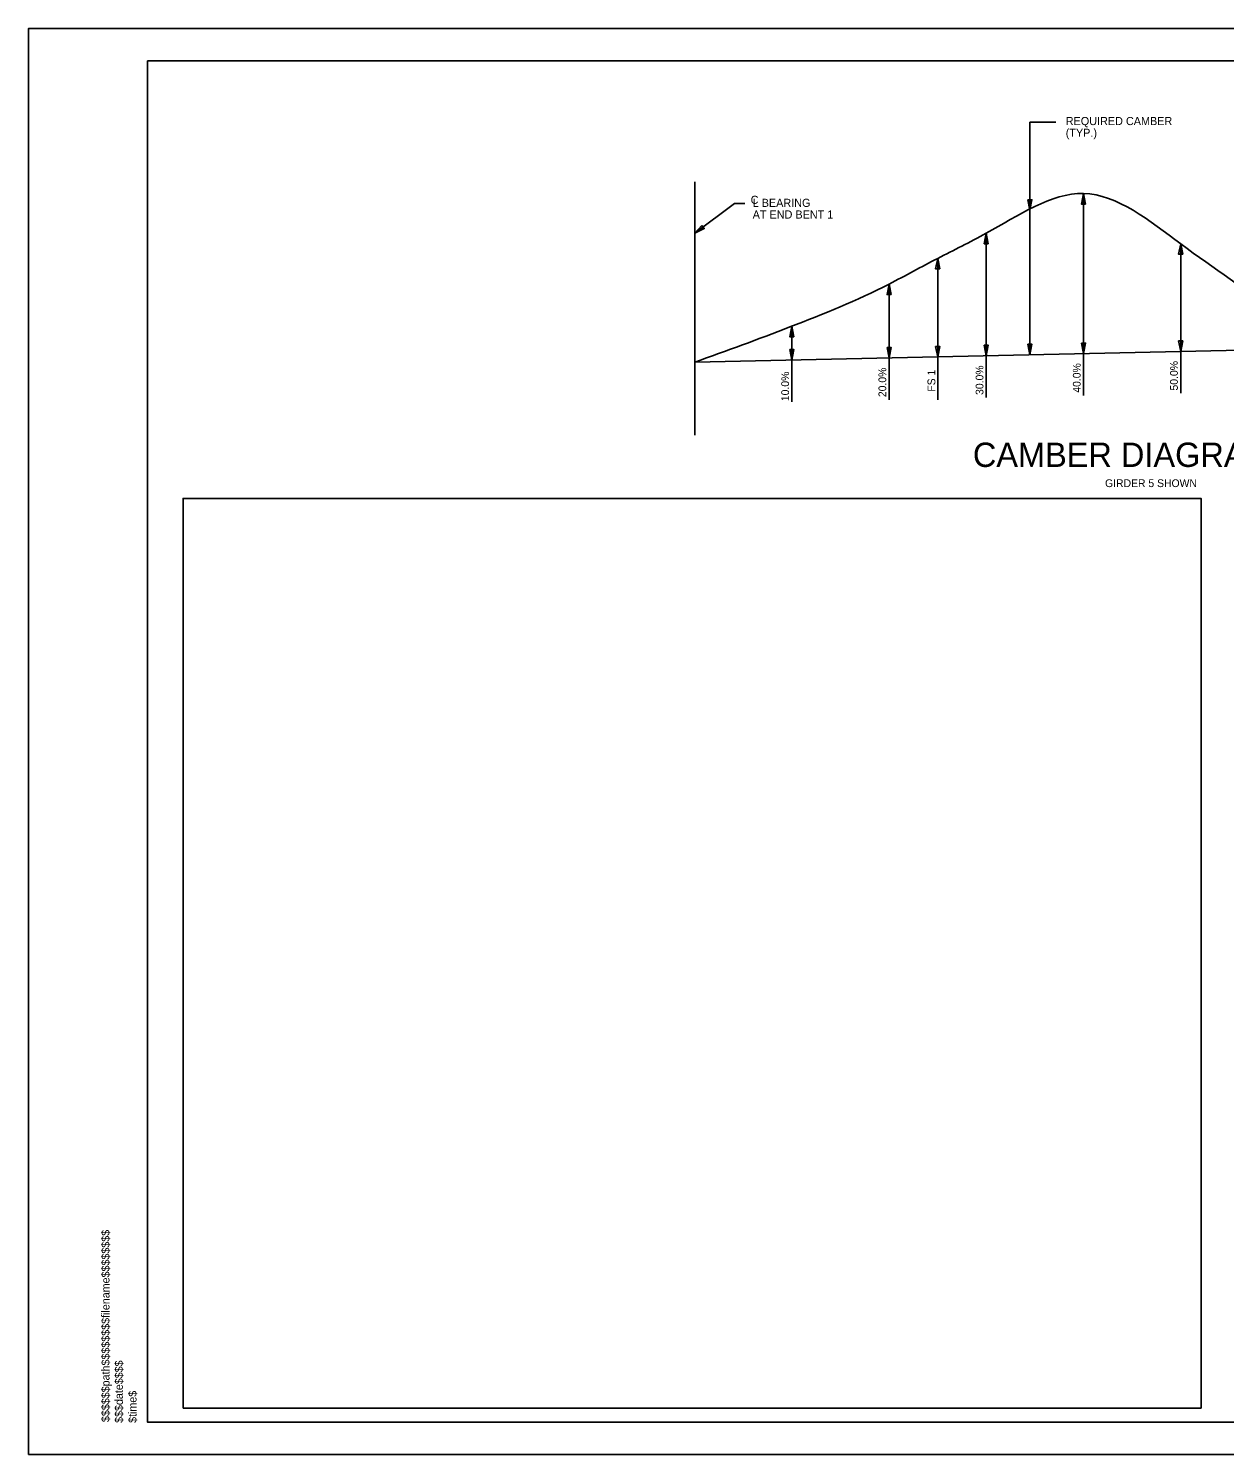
# Model space of a CAD drawing. Extents: x -125.5 to -89.4, y -5.1 to 16.9.
# Drawn here: x -125.53 to -107.08, y -5.07 to 16.93 of the extents above; entities that cross this region are included whole.
import ezdxf

# ---------------------------------------------------------------- set-up
doc = ezdxf.new("R2010")
doc.units = 0
for name, color, linetype in [('BR_AUTO DIMENSION', 7, 'Continuous'), ('BR_BORDER LINES', 7, 'Continuous'), ('BR_CENTER LINES', 7, 'Continuous'), ('BR_TABLE LINES', 7, 'Continuous'), ('BR_TEXT', 7, 'Continuous'), ('Level 31', 7, 'Continuous'), ('RD_SHT_ID', 7, 'Continuous')]:
    doc.layers.add(name, color=color, linetype=linetype)

msp = doc.modelspace()

# ---------------------------------------------------------------- linework, layer by layer
at = {"layer": 'BR_AUTO DIMENSION'}
for p, q in [((-110.08, 15.488), (-109.678, 15.488)), ((-110.08, 11.9), (-110.08, 15.488)), ((-114.641, 14.234), (-115.253, 13.776)), ((-114.481, 14.234), (-114.641, 14.234))]:
    msp.add_line(p, q, dxfattribs=at)
for points in [[(-109.222, 14.226), (-109.253, 14.389), (-109.285, 14.226)], [(-110.112, 14.293), (-110.08, 14.13), (-110.049, 14.293)], [(-115.141, 13.897), (-115.253, 13.776), (-115.104, 13.846)], [(-110.722, 13.612), (-110.753, 13.775), (-110.785, 13.612)], [(-107.722, 13.45), (-107.753, 13.612), (-107.785, 13.45)], [(-111.472, 13.225), (-111.503, 13.388), (-111.535, 13.225)], [(-112.222, 12.829), (-112.253, 12.991), (-112.285, 12.829)], [(-113.722, 12.178), (-113.753, 12.34), (-113.785, 12.178)], [(-107.785, 12.115), (-107.753, 11.952), (-107.722, 12.115)], [(-113.785, 11.98), (-113.753, 11.817), (-113.722, 11.98)], [(-112.285, 12.014), (-112.253, 11.851), (-112.222, 12.014)], [(-111.535, 12.03), (-111.503, 11.868), (-111.472, 12.03)], [(-110.785, 12.047), (-110.753, 11.885), (-110.722, 12.047)], [(-110.112, 12.062), (-110.08, 11.9), (-110.049, 12.062)], [(-109.285, 12.081), (-109.253, 11.919), (-109.222, 12.081)]]:
    msp.add_lwpolyline(points, close=True, dxfattribs=at)
at = {"layer": 'BR_BORDER LINES'}
for p, q in [((-90.033, 16.434), (-123.699, 16.434)), ((-123.699, -4.566), (-123.699, 16.434)), ((-123.699, -4.566), (-90.033, -4.566))]:
    msp.add_line(p, q, dxfattribs=at)
at = {"layer": 'BR_CENTER LINES'}
msp.add_line((-115.253, 10.659), (-115.253, 14.566), dxfattribs=at)
at = {"layer": 'BR_TABLE LINES'}
for p, q in [((-109.253, 11.274), (-109.253, 14.389)), ((-110.753, 11.24), (-110.753, 13.775)), ((-107.753, 11.308), (-107.753, 13.612)), ((-111.503, 11.207), (-111.503, 13.388)), ((-112.253, 11.207), (-112.253, 12.991)), ((-113.753, 11.173), (-113.753, 12.34)), ((-115.253, 11.784), (-100.257, 12.121))]:
    msp.add_line(p, q, dxfattribs=at)
for points in [[(-123.699, 16.434), (-90.033, 16.434), (-90.033, -4.566), (-123.699, -4.566)], [(-123.148, -4.349), (-107.438, -4.349), (-107.438, 9.685), (-123.148, 9.685)]]:
    msp.add_lwpolyline(points, close=True, dxfattribs=at)
msp.add_spline([(-115.253, 11.784), (-113.783, 12.329), (-112.253, 12.991), (-111.503, 13.388), (-110.753, 13.775), (-109.253, 14.389), (-107.753, 13.612), (-106.253, 12.546), (-104.753, 11.48), (-103.702, 10.932), (-103.253, 10.754), (-101.753, 10.797), (-100.257, 12.121)], degree=3, dxfattribs=at)
at = {"layer": 'Level 31'}
msp.add_lwpolyline([(-125.533, -5.066), (-89.533, -5.066), (-89.533, 16.934), (-125.533, 16.934)], close=True, dxfattribs=at)

# ---------------------------------------------------------------- texts
at = {"layer": 'BR_AUTO DIMENSION'}
for s, p in [('REQUIRED CAMBER', (-109.527, 15.444)), ('(TYP.)', (-109.527, 15.263)), ('C', (-114.389, 14.229)), ('L BEARING', (-114.358, 14.182)), ('AT END BENT 1', (-114.358, 14.002))]:
    msp.add_text(s, height=0.125, dxfattribs=at).set_placement(p)
at = {"layer": 'BR_TEXT'}
for s, p in [('20.0%', (-112.297, 11.247)), ('FS 1', (-111.54, 11.331)), ('30.0%', (-110.797, 11.281)), ('40.0%', (-109.297, 11.315)), ('50.0%', (-107.797, 11.349)), ('10.0%', (-113.797, 11.185))]:
    msp.add_text(s, height=0.12, rotation=90, dxfattribs=at).set_placement(p)
for s, height, p in [('CAMBER DIAGRAM - SPAN A', 0.375, (-110.96, 10.17)), ('GIRDER 5 SHOWN', 0.12, (-108.92, 9.859))]:
    msp.add_text(s, height=height, dxfattribs=at).set_placement(p)
at = {"layer": 'RD_SHT_ID'}
for s, height, p in [('$$$$$$path$$$$$$$$filename$$$$$$$$', 0.12347, (-124.283, -4.566)), ('$$$date$$$$', 0.12347, (-124.077, -4.579)), ('$time$', 0.1235, (-123.866, -4.579))]:
    msp.add_text(s, height=height, rotation=90, dxfattribs=at).set_placement(p)

doc.saveas('drawing.dxf')
